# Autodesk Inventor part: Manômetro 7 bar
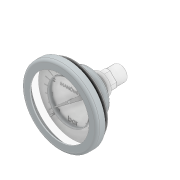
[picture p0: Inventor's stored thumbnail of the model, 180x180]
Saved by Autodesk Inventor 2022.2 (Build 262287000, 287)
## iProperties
Created: 2009-08
Part Number: Manômetro 7 bar
Material: Materiais Bomval|AISI 316
Document SubType Name: Modeling
Designer: 18907419
Density: 8 g/cm^3
Appearance: Default
Author: 18907419
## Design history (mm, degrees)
feature "Solido1"
feature "Solido2:1"
feature "Solido3:1"
feature "Solido4:1"
feature "Solido5:1"
feature "Solido6:1"
feature "Solido7:1"
feature "Solido8:1"
feature "Solido9:1"
feature "Solido10:1"
feature "Solido11:1"
feature "Solido12:1"
feature "Solido13:1"
feature "Solido14:1"
feature "Solido15:1"
feature "Solido16:1"
feature "Solido17:1"
feature "Solido18:1"
feature "Solido19:1"
feature "Solido20:1"
feature "Solido21:1"
feature "Solido22:1"
feature "Solido23:1"
feature "Solido24:1"
feature "Solido25:1"
feature "Solido26:1"
feature "Solido27:1"
feature "Solido28:1"
feature "Solido29:1"
feature "Solido30:1"
feature "Solido31:1"
feature "Solido32:1"
feature "Solido33:1"
feature "Solido34:1"
feature "Solido35:1"
feature "Solido36:1"
feature "Solido37:1"
feature "Solido38:1"
feature "Solido39:1"
feature "Solido40:1"
feature "Solido41:1"
feature "Solido42:1"
feature "Solido43:1"
feature "Solido44:1"
feature "Solido45:1"
feature "Solido46:1"
feature "Solido47:1"
feature "Solido48:1"
feature "Solido49:1"
node "Modifica diretta1"
node "Solido2"
node "Solido3"
node "Solido4"
node "Solido5"
node "Solido6"
node "Solido7"
node "Solido8"
node "Solido9"
node "Solido10"
node "Solido11"
node "Solido12"
node "Solido13"
node "Solido14"
node "Solido15"
node "Solido16"
node "Solido17"
node "Solido18"
node "Solido19"
node "Solido20"
node "Solido21"
node "Solido22"
node "Solido23"
node "Solido24"
node "Solido25"
node "Solido26"
node "Solido27"
node "Solido28"
node "Solido29"
node "Solido30"
node "Solido31"
node "Solido32"
node "Solido33"
node "Solido34"
node "Solido35"
node "Solido36"
node "Solido37"
node "Solido38"
node "Solido39"
node "Solido40"
node "Solido41"
node "Solido42"
node "Solido43"
node "Solido44"
node "Solido45"
node "Solido46"
node "Solido47"
node "Solido48"
node "Solido49"
node "Solido50"
feature "Scala1"
other parameters: "d0" = 6
